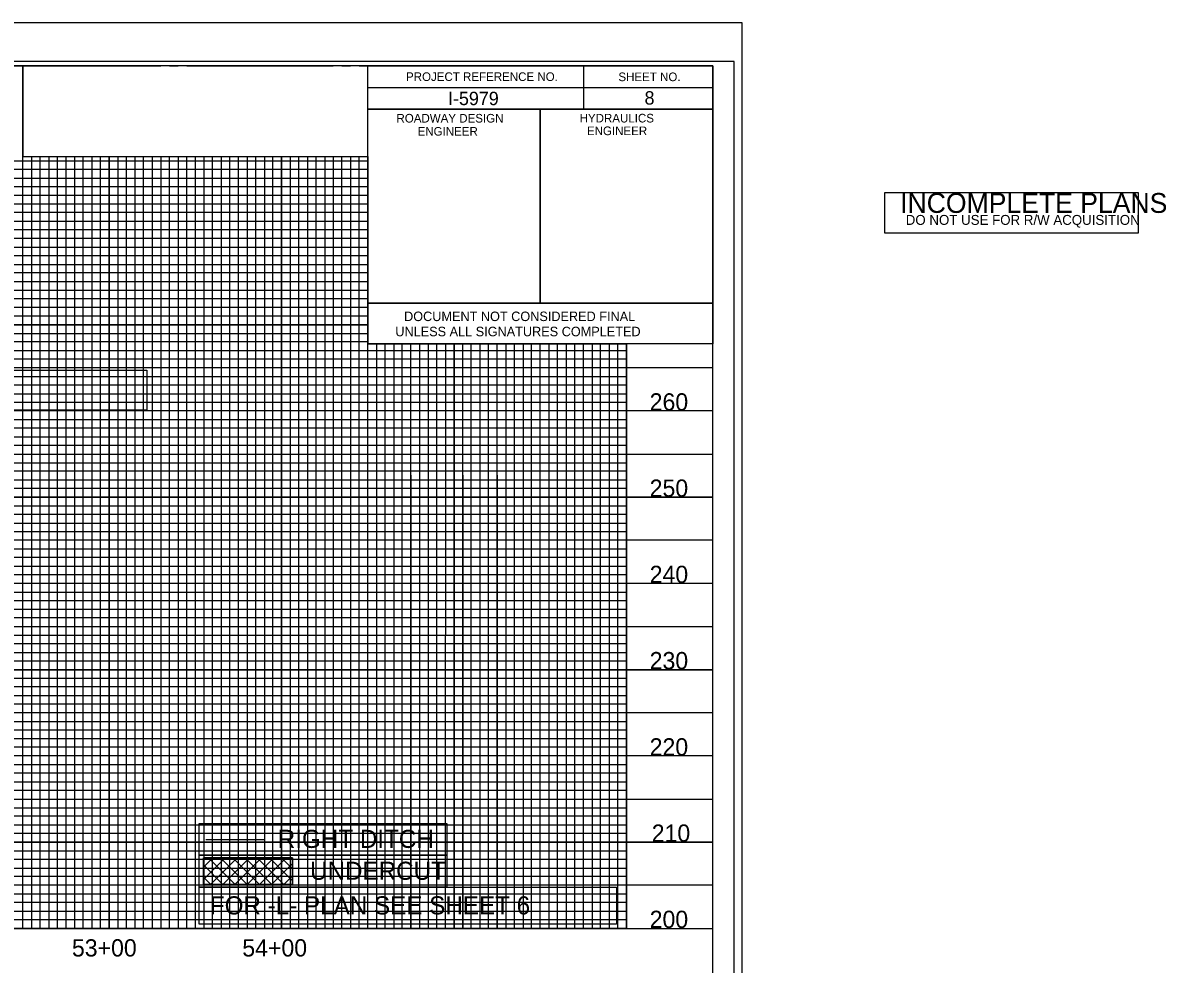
# Model space of a CAD drawing. Extents: x 1810963 to 1812908, y 722070 to 723170.
# Drawn here: x 1812230 to 1812893, y 722624 to 723170 of the extents above; entities that cross this region are included whole.
import ezdxf

# ---------------------------------------------------------------- set-up
doc = ezdxf.new("R2010")
doc.units = 0
for name, color, linetype in [('Exist Horizontal Alignment Tick Label', 7, 'Continuous'), ('Old_Level_11', 7, 'Continuous'), ('Old_Level_2', 7, 'Continuous'), ('Prop Conc 2ft 6in Curb and Gutter', 7, 'Continuous'), ('Prop Dimension Text', 7, 'Continuous'), ('Prop Grid Mask', 7, 'Continuous'), ('Prop Horizontal Alignment Station Label', 7, 'Continuous'), ('Prop RDY Traffic Signal CELL', 7, 'Continuous'), ('Prop Shade Heavy', 7, 'Continuous'), ('Prop Shade Light', 7, 'Continuous'), ('Prop Vertical Profile Ditch Grade Right', 7, 'Continuous'), ('Scratch_Level_0', 7, 'Continuous'), ('Scratch_Level_3', 7, 'Continuous'), ('Scratch_Level_5', 7, 'Continuous'), ('Sheet Block Title CELL', 7, 'Continuous'), ('Sheet North Arrow CELL', 7, 'Continuous'), ('Sheet Symbology CELL', 7, 'Continuous'), ('Sheet Title CELL', 7, 'Continuous')]:
    doc.layers.add(name, color=color, linetype=linetype)

msp = doc.modelspace()

# ---------------------------------------------------------------- linework, layer by layer
at = {"layer": 'Old_Level_11'}
msp.add_lwpolyline([(1810976.46, 722092.33), (1812642.96, 722092.33), (1812642.96, 723147.43), (1810976.46, 723147.43)], close=True, dxfattribs=at)
at = {"layer": 'Old_Level_2'}
for points in [[(1812210.84, 722968.52), (1812302.42, 722968.52), (1812302.42, 722945.34), (1812210.84, 722945.34)], [(1812332.66, 722705.78), (1812476.33, 722705.78), (1812476.33, 722687.29), (1812332.66, 722687.29)], [(1812332.66, 722687.29), (1812476.33, 722687.29), (1812476.33, 722668.81), (1812332.66, 722668.81)], [(1812332.66, 722668.81), (1812574.68, 722668.81), (1812574.68, 722647.28), (1812332.66, 722647.28)]]:
    msp.add_lwpolyline(points, close=True, dxfattribs=at)
at = {"layer": 'Prop Conc 2ft 6in Curb and Gutter'}
for p, q in [((1812230.46, 722644.88), (1812230.46, 723144.88)), ((1812280.46, 722644.88), (1812280.46, 723092.45)), ((1812330.46, 722644.88), (1812330.46, 723092.45)), ((1812380.46, 722644.88), (1812380.46, 723092.45)), ((1812430.41, 723044.88), (1811130.46, 723044.88)), ((1812430.46, 722644.88), (1812430.46, 723007.33)), ((1812430.46, 722994.88), (1811130.46, 722994.88)), ((1812480.46, 722644.88), (1812480.46, 722983.83)), ((1812530.46, 722644.88), (1812530.46, 722983.83)), ((1812580.46, 722644.88), (1812580.46, 722983.83)), ((1812630.46, 722944.88), (1811130.46, 722944.88)), ((1812630.46, 722894.88), (1811130.46, 722894.88)), ((1812630.46, 722844.88), (1811130.46, 722844.88)), ((1812630.46, 722794.88), (1811130.46, 722794.88)), ((1812630.46, 722744.88), (1811130.46, 722744.88)), ((1812630.46, 722694.88), (1811130.46, 722694.88))]:
    msp.add_line(p, q, dxfattribs=at)
at = {"layer": 'Prop Dimension Text'}
for p, q in [((1812430.41, 722983.83), (1812430.41, 723007.33)), ((1812430.41, 723007.33), (1812630.45, 723007.33)), ((1812430.41, 722983.83), (1812430.41, 723007.33)), ((1812430.41, 723007.33), (1812630.45, 723007.33)), ((1812630.45, 723007.32), (1812630.45, 722983.82)), ((1812630.45, 723007.32), (1812630.45, 722983.82)), ((1812630.45, 722983.83), (1812430.41, 722983.83)), ((1812630.45, 722983.83), (1812430.41, 722983.83))]:
    msp.add_line(p, q, dxfattribs=at)
at = {"layer": 'Prop Horizontal Alignment Station Label'}
msp.add_lwpolyline([(1812730.17, 723048.01), (1812730.17, 723071.51), (1812877.17, 723071.51), (1812877.17, 723048.01)], close=True, dxfattribs=at)
at = {"layer": 'Prop RDY Traffic Signal CELL'}
msp.add_line((1812647.46, 723169.88), (1810963.46, 723169.88), dxfattribs=at)
at = {"layer": 'Prop Shade Heavy'}
for points in [[(1812180.46, 722644.88), (1812230.46, 722644.88), (1812230.46, 723144.88), (1812280.46, 723144.88)], [(1812330.46, 723144.88), (1812380.46, 723144.88)], [(1812380.46, 723092.45), (1812380.46, 722644.88), (1812430.46, 722644.88), (1812430.46, 723144.88), (1812456.76, 723144.88)], [(1812280.46, 723092.45), (1812280.46, 722644.88), (1812330.46, 722644.88), (1812330.46, 723092.45)], [(1812430.46, 723044.88), (1811130.46, 723044.88), (1811130.46, 722994.88), (1812430.46, 722994.88)], [(1812580.46, 722983.83), (1812580.46, 722644.88), (1812630.46, 722644.88), (1812630.46, 722994.88)], [(1812480.46, 722983.83), (1812480.46, 722644.88), (1812530.46, 722644.88), (1812530.46, 722644.88), (1812530.46, 722983.83)], [(1812630.46, 722944.88), (1811130.46, 722944.88), (1811130.46, 722894.88), (1812630.46, 722894.88)], [(1812630.46, 722844.88), (1811130.46, 722844.88), (1811130.46, 722794.88), (1812630.46, 722794.88)], [(1812630.46, 722744.88), (1811130.46, 722744.88), (1811130.46, 722744.88), (1811130.46, 722694.88), (1812630.46, 722694.88)]]:
    msp.add_lwpolyline(points, dxfattribs=at)
at = {"layer": 'Prop Shade Light'}
for p, q in [((1812255.46, 723144.88), (1812305.46, 723144.88)), ((1812355.46, 723144.88), (1812405.46, 723144.88)), ((1812255.46, 722644.88), (1812255.46, 723092.45)), ((1812305.46, 723092.45), (1812305.46, 722644.88)), ((1812355.46, 722644.88), (1812355.46, 723092.45)), ((1812405.46, 723092.45), (1812405.46, 722644.88)), ((1812455.46, 722644.88), (1812455.46, 722983.83)), ((1812205.46, 722644.88), (1812255.46, 722644.88)), ((1812305.46, 722644.88), (1812355.46, 722644.88)), ((1812405.46, 722644.88), (1812455.46, 722644.88))]:
    msp.add_line(p, q, dxfattribs=at)
for points in [[(1812430.46, 723069.88), (1811130.46, 723069.88), (1811130.46, 723019.88), (1812430.46, 723019.88)], [(1812455.46, 722907.68), (1812455.46, 722644.88), (1812505.46, 722644.88), (1812505.46, 722983.83)], [(1812505.46, 722907.68), (1812505.46, 722644.88), (1812555.46, 722644.88), (1812555.46, 722983.83)], [(1812630.46, 722969.88), (1811130.46, 722969.88), (1811130.46, 722919.88), (1812455.46, 722919.88)], [(1812455.46, 722919.88), (1812630.46, 722919.88)], [(1812630.46, 722869.88), (1811130.46, 722869.88), (1811130.46, 722819.88), (1812630.46, 722819.88)], [(1812630.46, 722769.88), (1811130.46, 722769.88), (1811130.46, 722719.88), (1812630.46, 722719.88)], [(1812630.46, 722669.88), (1811130.46, 722669.88)]]:
    msp.add_lwpolyline(points, dxfattribs=at)
at = {"layer": 'Prop Vertical Profile Ditch Grade Right'}
for p, q in [((1812336.57, 722696.47), (1812370.21, 722696.47)), ((1812335.11, 722673.22), (1812347.67, 722685.78)), ((1812335.11, 722680.29), (1812340.6, 722685.78)), ((1812386.81, 722685.78), (1812335.11, 722685.78)), ((1812335.11, 722685.78), (1812335.11, 722670.34)), ((1812335.11, 722681.65), (1812346.42, 722670.34)), ((1812338.05, 722685.78), (1812353.49, 722670.34)), ((1812339.3, 722670.34), (1812354.74, 722685.78)), ((1812345.12, 722685.78), (1812360.56, 722670.34)), ((1812346.37, 722670.34), (1812361.81, 722685.78)), ((1812352.19, 722685.78), (1812367.64, 722670.34)), ((1812353.44, 722670.34), (1812368.88, 722685.78)), ((1812359.27, 722685.78), (1812374.71, 722670.34)), ((1812360.51, 722670.34), (1812375.95, 722685.78)), ((1812366.34, 722685.78), (1812381.78, 722670.34)), ((1812367.58, 722670.34), (1812383.02, 722685.78)), ((1812373.41, 722685.78), (1812386.81, 722672.37)), ((1812374.65, 722670.34), (1812386.81, 722682.5)), ((1812380.48, 722685.78), (1812386.81, 722679.44)), ((1812386.81, 722670.34), (1812386.81, 722685.78)), ((1812335.11, 722674.58), (1812339.35, 722670.34)), ((1812381.72, 722670.34), (1812386.81, 722675.43)), ((1812335.11, 722670.34), (1812386.81, 722670.34))]:
    msp.add_line(p, q, dxfattribs=at)
msp.add_lwpolyline([(1812335.11, 722685.78), (1812386.81, 722685.78), (1812386.81, 722670.34), (1812335.11, 722670.34)], close=True, dxfattribs=at)
at = {"layer": 'Scratch_Level_3'}
msp.add_lwpolyline([(1811180.46, 723144.88), (1812230.46, 723144.88), (1812230.46, 723092.45), (1812430.5, 723092.45), (1812430.41, 722983.83), (1812580.46, 722983.83), (1812580.46, 722644.88), (1811180.46, 722644.88)], close=True, dxfattribs=at)
at = {"layer": 'Scratch_Level_5'}
msp.add_lwpolyline([(1811180.46, 722983.83), (1811180.46, 722644.88), (1812580.46, 722644.88), (1812580.46, 722983.83)], dxfattribs=at)
at = {"layer": 'Sheet North Arrow CELL'}
msp.add_lwpolyline([(1810963.46, 722069.88), (1812647.46, 722069.88), (1812647.46, 723169.88), (1810963.46, 723169.88)], close=True, dxfattribs=at)
at = {"layer": 'Sheet Symbology CELL'}
for p, q in [((1812555.46, 723144.83), (1812555.46, 723119.83)), ((1812430.41, 723132.33), (1812630.46, 723132.33)), ((1812530.46, 723119.83), (1812530.46, 723007.38)), ((1811130.46, 722644.88), (1812630.46, 722644.88))]:
    msp.add_line(p, q, dxfattribs=at)
for points in [[(1812630.46, 723144.88), (1811130.46, 723144.88), (1811130.46, 722094.88), (1812630.46, 722094.88)], [(1812430.41, 723144.88), (1812630.46, 723144.88), (1812630.46, 723119.83), (1812430.41, 723119.83)], [(1812430.41, 723119.83), (1812530.46, 723119.83), (1812530.46, 723007.33), (1812430.41, 723007.33)], [(1812530.46, 723119.83), (1812630.46, 723119.83), (1812630.46, 723007.33), (1812530.46, 723007.33)]]:
    msp.add_lwpolyline(points, close=True, dxfattribs=at)
at = {"layer": 'Sheet Title CELL'}
for p, q in [((1812225.46, 723144.88), (1812235.46, 723144.88)), ((1812240.46, 723144.88), (1812245.46, 723144.88)), ((1812250.46, 723144.88), (1812260.46, 723144.88)), ((1812265.46, 723144.88), (1812270.46, 723144.88)), ((1812275.46, 723144.88), (1812285.46, 723144.88)), ((1812290.46, 723144.88), (1812295.46, 723144.88)), ((1812300.46, 723144.88), (1812310.46, 723144.88)), ((1812315.46, 723144.88), (1812320.46, 723144.88)), ((1812235.46, 723092.45), (1812235.46, 722644.88)), ((1812240.46, 722644.88), (1812240.46, 723092.45)), ((1812245.46, 723092.45), (1812245.46, 722644.88)), ((1812250.46, 722644.88), (1812250.46, 723092.45)), ((1812260.46, 723092.45), (1812260.46, 722644.88)), ((1812265.46, 722644.88), (1812265.46, 723092.45)), ((1812270.46, 723092.45), (1812270.46, 722644.88)), ((1812275.46, 722644.88), (1812275.46, 723092.45)), ((1812285.46, 723092.45), (1812285.46, 722644.88)), ((1812290.46, 722644.88), (1812290.46, 723092.45)), ((1812295.46, 723092.45), (1812295.46, 722644.88)), ((1812300.46, 722644.88), (1812300.46, 723092.45)), ((1812310.46, 723092.45), (1812310.46, 722644.88)), ((1812315.46, 722644.88), (1812315.46, 723092.45)), ((1812320.46, 723092.45), (1812320.46, 722644.88)), ((1811180.46, 723089.88), (1812430.46, 723089.88)), ((1812430.41, 723009.88), (1811180.46, 723009.88)), ((1812430.46, 723004.88), (1811180.46, 723004.88)), ((1812430.46, 722999.88), (1811180.46, 722999.88)), ((1811180.46, 722989.88), (1812430.46, 722989.88)), ((1812430.46, 722984.88), (1811180.46, 722984.88)), ((1811180.46, 722979.88), (1812580.46, 722979.88)), ((1812580.46, 722959.88), (1811180.46, 722959.88)), ((1811180.46, 722954.88), (1812580.46, 722954.88)), ((1812580.46, 722934.88), (1811180.46, 722934.88)), ((1811180.46, 722929.88), (1812580.46, 722929.88)), ((1812580.46, 722909.88), (1811180.46, 722909.88)), ((1811180.46, 722904.88), (1812580.46, 722904.88)), ((1812580.46, 722899.88), (1811180.46, 722899.88)), ((1811180.46, 722889.88), (1812580.46, 722889.88)), ((1812580.46, 722884.88), (1811180.46, 722884.88)), ((1811180.46, 722879.88), (1812580.46, 722879.88)), ((1812580.46, 722874.88), (1811180.46, 722874.88)), ((1811180.46, 722864.88), (1812580.46, 722864.88)), ((1812580.46, 722859.88), (1811180.46, 722859.88)), ((1811180.46, 722854.88), (1812580.46, 722854.88)), ((1812580.46, 722849.88), (1811180.46, 722849.88)), ((1811180.46, 722839.88), (1812580.46, 722839.88)), ((1812580.46, 722834.88), (1811180.46, 722834.88)), ((1811180.46, 722829.88), (1812580.46, 722829.88)), ((1812580.46, 722824.88), (1811180.46, 722824.88)), ((1811180.46, 722814.88), (1812580.46, 722814.88)), ((1812580.46, 722809.88), (1811180.46, 722809.88)), ((1811180.46, 722804.88), (1812580.46, 722804.88)), ((1812580.46, 722799.88), (1811180.46, 722799.88)), ((1811180.46, 722789.88), (1812580.46, 722789.88)), ((1812580.46, 722784.88), (1811180.46, 722784.88)), ((1811180.46, 722779.88), (1812580.46, 722779.88)), ((1812580.46, 722774.88), (1811180.46, 722774.88)), ((1811180.46, 722764.88), (1812580.46, 722764.88)), ((1812580.46, 722759.88), (1811180.46, 722759.88)), ((1812580.46, 722754.88), (1811180.46, 722754.88)), ((1812580.46, 722749.88), (1811180.46, 722749.88)), ((1811180.46, 722739.88), (1812580.46, 722739.88)), ((1812580.46, 722734.88), (1811180.46, 722734.88)), ((1811180.46, 722729.88), (1812580.46, 722729.88)), ((1812580.46, 722724.88), (1811180.46, 722724.88)), ((1811180.46, 722714.88), (1812580.46, 722714.88)), ((1812580.46, 722709.88), (1811180.46, 722709.88)), ((1811180.46, 722704.88), (1812580.46, 722704.88)), ((1812580.46, 722699.88), (1811180.46, 722699.88)), ((1811180.46, 722689.88), (1812580.46, 722689.88)), ((1812580.46, 722684.88), (1811180.46, 722684.88)), ((1811180.46, 722679.88), (1812580.46, 722679.88)), ((1812580.46, 722674.88), (1811180.46, 722674.88)), ((1811180.46, 722664.88), (1812580.46, 722664.88)), ((1812580.46, 722659.88), (1811180.46, 722659.88)), ((1811180.46, 722654.88), (1812580.46, 722654.88)), ((1812235.46, 722644.88), (1812240.46, 722644.88)), ((1812245.46, 722644.88), (1812250.46, 722644.88)), ((1812260.46, 722644.88), (1812265.46, 722644.88)), ((1812270.46, 722644.88), (1812275.46, 722644.88)), ((1812285.46, 722644.88), (1812290.46, 722644.88)), ((1812295.46, 722644.88), (1812300.46, 722644.88)), ((1812310.46, 722644.88), (1812315.46, 722644.88))]:
    msp.add_line(p, q, dxfattribs=at)
for points in [[(1812325.46, 723144.88), (1812335.46, 723144.88)], [(1812340.46, 723144.88), (1812345.46, 723144.88)], [(1812350.46, 723144.88), (1812360.46, 723144.88)], [(1812365.46, 723144.88), (1812370.46, 723144.88)], [(1812375.46, 723144.88), (1812385.46, 723144.88)], [(1812390.46, 723144.88), (1812395.46, 723144.88)], [(1812400.46, 723144.88), (1812410.46, 723144.88)], [(1812415.46, 723144.88), (1812420.46, 723144.88)], [(1812425.46, 723144.88), (1812435.46, 723144.88)], [(1812320.46, 722644.88), (1812325.46, 722644.88), (1812325.46, 723092.45)], [(1812335.46, 723092.45), (1812335.46, 722644.88), (1812340.46, 722644.88), (1812340.46, 723092.45)], [(1812345.46, 723092.45), (1812345.46, 722644.88), (1812350.46, 722644.88), (1812350.46, 723092.45)], [(1812360.46, 723092.45), (1812360.46, 722644.88), (1812365.46, 722644.88), (1812365.46, 723092.45)], [(1812370.46, 723092.45), (1812370.46, 722644.88), (1812375.46, 722644.88), (1812375.46, 723092.45)], [(1812385.46, 723092.45), (1812385.46, 722644.88), (1812390.46, 722644.88), (1812390.46, 723092.45)], [(1812395.46, 723092.45), (1812395.46, 722644.88), (1812400.46, 722644.88), (1812400.46, 723092.45)], [(1812410.46, 723092.45), (1812410.46, 722644.88), (1812415.46, 722644.88), (1812415.46, 723092.45)], [(1812420.46, 723092.45), (1812420.46, 722644.88), (1812425.46, 722644.88), (1812425.46, 723092.45)], [(1812430.46, 723084.88), (1811180.46, 723084.88), (1811180.46, 723079.88), (1812430.46, 723079.88)], [(1812430.46, 723074.88), (1811180.46, 723074.88), (1811180.46, 723064.88), (1812430.46, 723064.88)], [(1812430.46, 723059.88), (1811180.46, 723059.88), (1811180.46, 723054.88), (1812430.46, 723054.88)], [(1812430.46, 723049.88), (1811180.46, 723049.88), (1811180.46, 723039.88), (1812430.46, 723039.88)], [(1812430.46, 723034.78), (1811180.56, 723034.78), (1811180.56, 723029.88), (1812430.46, 723029.88)], [(1812430.46, 723024.88), (1811180.46, 723024.88), (1811180.46, 723014.88), (1812430.46, 723014.88)], [(1812435.46, 722983.83), (1812435.46, 722644.88), (1812440.46, 722644.88), (1812440.46, 722983.83)], [(1812445.46, 722983.83), (1812445.46, 722644.88), (1812450.46, 722644.88), (1812450.46, 722983.83)], [(1812460.46, 722983.83), (1812460.46, 722644.88), (1812460.46, 722644.88), (1812465.46, 722644.88), (1812470.46, 722644.88), (1812470.46, 722983.83)], [(1812465.46, 722983.83), (1812465.46, 722644.88)], [(1812475.45, 722983.83), (1812475.36, 722644.93), (1812480.36, 722644.93), (1812485.46, 722644.88), (1812485.46, 722983.83)], [(1812485.46, 722907.68), (1812485.46, 722644.88), (1812490.46, 722644.88), (1812490.46, 722983.83)], [(1812495.46, 722983.83), (1812495.46, 722644.88), (1812500.46, 722644.88), (1812500.46, 722983.83)], [(1812510.46, 722983.83), (1812510.46, 722644.88), (1812515.46, 722644.88), (1812515.46, 722983.83)], [(1812520.46, 722983.83), (1812520.46, 722644.88), (1812525.46, 722644.88), (1812525.46, 722983.83)], [(1812535.46, 722983.83), (1812535.46, 722644.88), (1812540.46, 722644.88), (1812540.46, 722983.83)], [(1812545.46, 722983.83), (1812545.46, 722644.88), (1812550.46, 722644.88), (1812550.46, 722983.83)], [(1812560.46, 722983.83), (1812560.46, 722644.88), (1812565.46, 722644.88), (1812565.46, 722983.83)], [(1812570.46, 722983.83), (1812570.46, 722644.88), (1812575.46, 722644.88), (1812575.46, 722983.83)], [(1812580.46, 722974.88), (1811180.46, 722974.88), (1811180.46, 722964.88), (1812580.46, 722964.88)], [(1812580.46, 722949.88), (1811180.46, 722949.88), (1811180.46, 722939.88), (1812580.46, 722939.88)], [(1812580.46, 722924.88), (1811180.46, 722924.88), (1811180.46, 722914.88), (1812580.46, 722914.88)], [(1812580.46, 722649.88), (1811180.46, 722649.88)]]:
    msp.add_lwpolyline(points, dxfattribs=at)

# ---------------------------------------------------------------- texts
at = {"layer": 'Exist Horizontal Alignment Tick Label'}
for s, p in [('RIGHT DITCH', (1812378.26, 722691.54)), ('UNDERCUT', (1812396.95, 722673.05)), ('FOR -L- PLAN SEE SHEET 6', (1812338.87, 722652.99))]:
    msp.add_text(s, height=10.5, rotation=360, dxfattribs=at).set_placement(p)
at = {"layer": 'Prop Dimension Text'}
for s, p in [('DOCUMENT NOT CONSIDERED FINAL', (1812451.48, 722996.99)), ('DOCUMENT NOT CONSIDERED FINAL', (1812451.48, 722996.99)), ('UNLESS ALL SIGNATURES COMPLETED', (1812446.41, 722988.19)), ('UNLESS ALL SIGNATURES COMPLETED', (1812446.41, 722988.19))]:
    msp.add_text(s, height=5.5, dxfattribs=at).set_placement(p)
at = {"layer": 'Prop Grid Mask'}
for s, p in [('8', (1812590.93, 723122.49)), ('I-5979', (1812476.99, 723122.19))]:
    msp.add_text(s, height=7.75, dxfattribs=at).set_placement(p)
at = {"layer": 'Prop Horizontal Alignment Station Label'}
for s, height, p in [('INCOMPLETE PLANS', 11.52, (1812739.12, 723059.71)), ('DO NOT USE FOR R/W ACQUISITION', 5.76, (1812742.37, 723052.76))]:
    msp.add_text(s, height=height, dxfattribs=at).set_placement(p)
at = {"layer": 'Scratch_Level_0'}
for s, p in [('260', (1812593.89, 722945.13)), ('250', (1812593.89, 722895.13)), ('240', (1812593.89, 722845.13)), ('230', (1812593.89, 722795.13)), ('220', (1812593.89, 722745.13)), ('210', (1812595.09, 722695.13)), ('200', (1812593.89, 722645.13))]:
    msp.add_text(s, height=10, dxfattribs=at).set_placement(p)
at = {"layer": 'Sheet Block Title CELL'}
for s, p in [('53+00', (1812258.9, 722628.6)), ('54+00', (1812357.68, 722628.6))]:
    msp.add_text(s, height=10, dxfattribs=at).set_placement(p)
at = {"layer": 'Sheet Symbology CELL'}
for s, height, p in [('PROJECT REFERENCE NO.', 5.0001, (1812452.62, 723136.19)), ('SHEET NO.', 5, (1812575.77, 723136.09)), ('ROADWAY DESIGN', 5.0001, (1812447.07, 723112.09)), ('HYDRAULICS', 5, (1812553.27, 723112.14)), ('ENGINEER', 5, (1812459.32, 723104.49)), ('ENGINEER', 5, (1812557.52, 723104.79))]:
    msp.add_text(s, height=height, dxfattribs=at).set_placement(p)

doc.saveas('drawing.dxf')
